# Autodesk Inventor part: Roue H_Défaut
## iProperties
Shininess: 64.0
Length Units: 11269
Angle Units: 11279
Time Units: 11290
Mass Units: 11283
Length Display Precision: 3
Angle Display Precision: 2
Compacted: True
Part Number: Roue H_Défaut
Document SubType Name: Modeling
Created: 2006-01
Material: Par défaut
Designer: Fricot
Density: 0.0
Volumn: 0.0
Area: 0.0
PropertySet Name: Model Information
Control State: 0
Master: False
Checked Out: False
Author: Fricot
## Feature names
1. Base1
